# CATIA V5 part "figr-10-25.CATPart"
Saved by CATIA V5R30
Part number: Part1
Bounding box of the stored display mesh (mm): x -92.502 to 25.581, y -200.404 to 0, z 0 to 47.305
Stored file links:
  D:\PROJECTS\CATIA V56R 2020\Resources\Parts File\c10_catia_v5_6r2020_prt\figr-10-25.CATPart
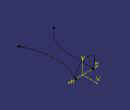
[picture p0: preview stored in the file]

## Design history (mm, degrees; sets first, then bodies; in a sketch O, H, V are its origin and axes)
Set1
  Sketch1 on xy-plane, origin (0, 0, 0), H (1, 0, 0), V (0, 1, 0)
    spline S1 through (-36.6295, 0) (-39.5961, -76.7629) (-56.6868, -154.7631) (-92.5015, -194.2587)
    point P1 (-36.6295, 0)
    coincidence: P1 H
  Sketch2 on xy-plane, origin (0, 0, 0), H (1, 0, 0), V (0, 1, 0)
    spline S1 through (25.5807, 0) (5.5021, -50.6307) (25.5807, -200.404)
    point P1 (25.5807, 0)
    coincidence: P1 H
  Sketch3 on zx-plane, origin (0, 0, 0), H (-1, 0, 0), V (0, 0, 1)
    spline S1 through (-25.5807, 0) (16.4189, 47.2175) (28.9802, 46.33) (36.6295, 0)
    reference projected point E1 (36.6295, 0) from vertex of Sketch1
    reference projected point E2 (-25.5807, 0) from vertex of Sketch2
    point P1 (-25.5807, 0)
    point P2 (36.6295, 0)
    coincidence: P1 H, P2 H, E1 P2, P1 E2
Body1 (main body)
